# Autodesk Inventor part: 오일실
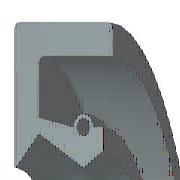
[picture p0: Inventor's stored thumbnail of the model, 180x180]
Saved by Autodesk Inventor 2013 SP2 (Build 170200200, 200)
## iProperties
IsCustomPart: 0
Created: 2009-02
Part Number: 오일실
Material: 고무
Description: 오일-실
Document SubType Name: Modeling
Standard: KS B 2804
Designer: KYOUNG IL JANG
Standards Organization: KS
Language: ko-KR
Size Designation: D - 20 32 8
Categories: <MemberInstance><Categories><Category DisplayName="샤프트 부품" InternalName="7f7aeb1f-a693-4053-b835-cee3144e0d98" Mnemonic="SHFT"><Category DisplayName="실링" Intern
Density: 0.93 g/cm^3
Mass: 2.19344 g
Surface Area: 31.4782 cm^2
Volume: 2.35853 cm^3
Author: KYOUNG IL JANG
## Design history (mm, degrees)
revolve "본체" stored, may be unused: angle "d17" = 90 deg
revolve "스프링1" stored, may be unused: angle "d18" = 90 deg
body "Solid1"
sketch "스케치1"
  geometry: L1 (0, 16)-(8, 16); L2 (8, 14.25)-(1.75, 14.25); L3 (1.75, 11.75)-(4.9, 10); L4 (4.9, 10)-(0, 10); L5 (0, 0)-(9.586, 0) reference; L6 (4.9, 10)-(6.3, 10.875); L7 (0, 18)-(0, -3) reference; L8 (-1.941, 0)-(11.507, 0) reference; L9 (4.2, 12.1)-(1.75, 12.71); L10 (1.75, 12.71)-(1.75, 14.25); L11 (0, 16)-(0, 10.088); L12 (4.9, 10)-(0, 10); L13 (1.75, 11.75)-(0.152, 10.028); L14 (8, 16)-(8, 14.25); L15 (5.6, 12.1)-(6.3, 12.1); L16 (6.3, 12.1)-(6.3, 10.875); C1 r 0.455 at (4.9, 12.1); A1 r 0.7 centre (4.9, 12.1) between (5.6, 12.1) and (4.2, 12.1); A2 r 0.088 centre (0.088, 10.088) between (0, 10.088) and (0.152, 10.028); 1 further point
  constraints: 28 end point, 5 horizontal alignment, 5 point on line, 4 point on circle, 4 vertical alignment, 3 centre point, 3 tangent, 2 collinear, 2 horizontal, 2 perpendicular, 1 coincident, 1 parallel
  dimensions: "d0" = 32 diameter of L1 L5 (= SD2); "d1" = 1.75 distance of L1.end L2.start (= SD); "d2" = 0.91 diameter of C1 (= SPDI); "d3" = 1.4 diameter of A1 (= SPDA); "d4" = 20 diameter of L3.end L5 (= NND); "d5" = 23.5 diameter of L3.start L5 (= TKDM); "d7" = 25.42 diameter of L9.end L5 (= TKDM + 0.24 x SWDT); "d8" = 1.75 distance between parallel lines of L11 L10 (= SD); "d9" = 4.9 distance from line of L11 C1.centre (= SPDST); "d10" = 24.2 diameter of C1.centre L5 (= HLDM); "d11" = 0.0875 radius of A2 (= 0.25 x LAB); "d12" = 6.3 distance between parallel lines of L11 L16 (= SDI); "d13" = 21.75 diameter of L6.end L5 (= ABDM); "d14" = 8 distance from line of L11 L1.end (= SWDT)
fillet "모깎기1" dims "d6" = 0.3 (= RR)
other parameters: "SD2" = 32 [user parameter; used in 1 equation term], "SWDT" = 8 [user parameter; used in 2 equation terms], "RR" = 0.3 [user parameter; used in 1 equation term], "SD" = 1.75 [user parameter; used in 2 equation terms], "NND" = 20 [user parameter; used in 1 equation term], "SPDA" = 1.4 [user parameter; used in 1 equation term], "SPDI" = 0.91 [user parameter; used in 1 equation term], "TKDM" = 23.5 [user parameter; used in 2 equation terms], "HLDM" = 24.2 [user parameter; used in 1 equation term], "ABDM" = 21.75 [user parameter; used in 1 equation term], "SDI" = 6.3 [user parameter; used in 1 equation term], "SPDST" = 4.9 [user parameter; used in 1 equation term], "LAB" = 0.35 [user parameter; used in 1 equation term], "d15" = 0, "d16" = 0, "d19" = 0
